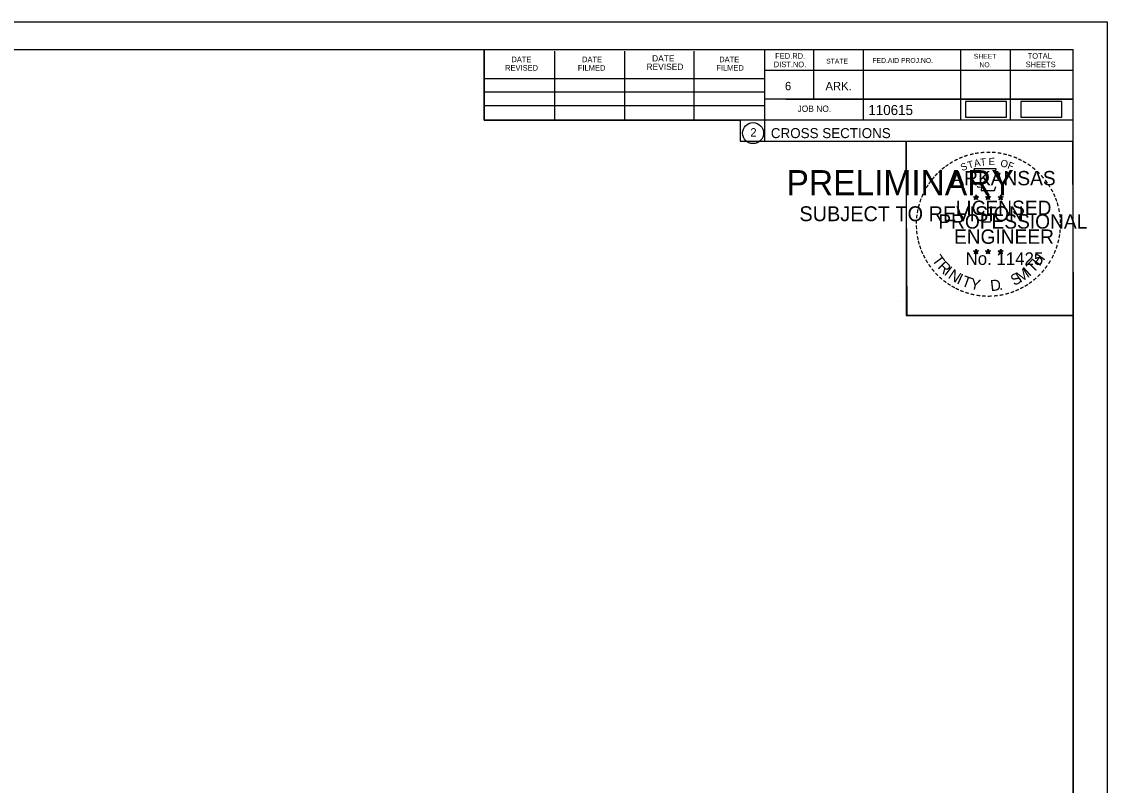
# Model space of a CAD drawing. Extents: x 1372132 to 1372465, y 380083 to 381790.
# Drawn here: x 1372313.3 to 1372464.9, y 381683.5 to 381790.2 of the extents above; entities that cross this region are included whole.
import ezdxf

# ---------------------------------------------------------------- set-up
doc = ezdxf.new("R2010")
doc.units = 0
for name, color, linetype in [('R_Border', 7, 'Continuous'), ('R_Border PE', 7, 'Continuous'), ('R_Border Prem', 7, 'Continuous'), ('R_Erosion', 7, 'Continuous'), ('R_No Plot', 7, 'Continuous')]:
    doc.layers.add(name, color=color, linetype=linetype)

msp = doc.modelspace()

# ---------------------------------------------------------------- linework, layer by layer
at = {"layer": 'R_Border'}
for p, q in [((1372144.01, 381786.3), (1372460.19, 381786.3)), ((1372377.93, 381776.42), (1372377.93, 381786.3)), ((1372387.79, 381776.42), (1372387.79, 381786.1)), ((1372397.55, 381776.42), (1372397.55, 381786.1)), ((1372407.23, 381776.42), (1372407.23, 381786.1)), ((1372417.09, 381786.3), (1372417.09, 381773.5)), ((1372423.93, 381786.3), (1372423.93, 381779.36)), ((1372430.87, 381786.3), (1372430.87, 381776.42)), ((1372444.45, 381786.3), (1372444.45, 381776.42)), ((1372451.39, 381786.3), (1372451.39, 381776.42)), ((1372460.19, 381580.84), (1372460.19, 381786.3)), ((1372377.93, 381782.28), (1372417.09, 381782.28)), ((1372460.19, 381783.36), (1372417.09, 381783.36)), ((1372460.19, 381783.38), (1372460.19, 381783.38)), ((1372377.93, 381780.42), (1372417.09, 381780.42)), ((1372460.19, 381779.36), (1372417.09, 381779.36)), ((1372420.05, 381779.36), (1372460.19, 381779.36)), ((1372377.93, 381776.42), (1372377.93, 381778.48)), ((1372377.93, 381778.48), (1372417.09, 381778.48)), ((1372460.19, 381776.42), (1372377.93, 381776.42)), ((1372417.09, 381773.5), (1372460.19, 381773.5))]:
    msp.add_line(p, q, dxfattribs=at)
msp.add_circle((1372415.48, 381774.63), 1.47, dxfattribs=at)
at = {"layer": 'R_Border PE'}
for p, q in [((1372446.28, 381765.75), (1372446.63, 381765.64)), ((1372446.28, 381765.75), (1372446.53, 381765.71)), ((1372446.28, 381765.75), (1372446.52, 381765.63)), ((1372446.41, 381765.35), (1372446.63, 381765.64)), ((1372446.41, 381765.35), (1372446.54, 381765.59)), ((1372446.41, 381765.35), (1372446.63, 381765.56)), ((1372446.63, 381766.01), (1372446.59, 381765.76)), ((1372446.63, 381765.64), (1372446.63, 381766.01)), ((1372446.63, 381766.01), (1372446.68, 381765.76)), ((1372446.98, 381765.75), (1372446.63, 381765.64)), ((1372446.84, 381765.35), (1372446.63, 381765.64)), ((1372446.84, 381765.35), (1372446.63, 381765.56)), ((1372446.98, 381765.75), (1372446.69, 381765.71)), ((1372446.84, 381765.35), (1372446.7, 381765.64)), ((1372446.98, 381765.75), (1372446.77, 381765.65)), ((1372447.95, 381765.75), (1372448.3, 381765.64)), ((1372447.95, 381765.75), (1372448.2, 381765.71)), ((1372447.95, 381765.75), (1372448.19, 381765.63)), ((1372448.08, 381765.35), (1372448.3, 381765.64)), ((1372448.08, 381765.35), (1372448.21, 381765.59)), ((1372448.08, 381765.35), (1372448.3, 381765.56)), ((1372448.3, 381766.01), (1372448.26, 381765.76)), ((1372448.3, 381765.64), (1372448.3, 381766.01)), ((1372448.3, 381766.01), (1372448.35, 381765.76)), ((1372448.65, 381765.75), (1372448.3, 381765.64)), ((1372448.51, 381765.35), (1372448.3, 381765.64)), ((1372448.51, 381765.35), (1372448.3, 381765.56)), ((1372448.65, 381765.75), (1372448.36, 381765.71)), ((1372448.51, 381765.35), (1372448.37, 381765.64)), ((1372448.65, 381765.75), (1372448.44, 381765.65)), ((1372449.71, 381765.74), (1372450.06, 381765.63)), ((1372449.71, 381765.74), (1372449.97, 381765.7)), ((1372449.71, 381765.74), (1372449.95, 381765.62)), ((1372449.85, 381765.33), (1372450.06, 381765.63)), ((1372449.85, 381765.33), (1372449.97, 381765.58)), ((1372449.85, 381765.33), (1372450.06, 381765.55)), ((1372450.06, 381766), (1372450.02, 381765.74)), ((1372450.06, 381765.63), (1372450.06, 381766)), ((1372450.06, 381766), (1372450.11, 381765.75)), ((1372450.41, 381765.74), (1372450.06, 381765.63)), ((1372450.28, 381765.33), (1372450.06, 381765.63)), ((1372450.28, 381765.33), (1372450.06, 381765.55)), ((1372450.41, 381765.74), (1372450.12, 381765.69)), ((1372450.28, 381765.33), (1372450.14, 381765.63)), ((1372450.41, 381765.74), (1372450.21, 381765.64)), ((1372446.28, 381758.18), (1372446.62, 381758.07)), ((1372446.28, 381758.18), (1372446.53, 381758.14)), ((1372446.28, 381758.18), (1372446.51, 381758.06)), ((1372446.41, 381757.77), (1372446.62, 381758.07)), ((1372446.41, 381757.77), (1372446.53, 381758.02)), ((1372446.41, 381757.77), (1372446.62, 381757.99)), ((1372446.62, 381758.44), (1372446.58, 381758.18)), ((1372446.62, 381758.07), (1372446.62, 381758.44)), ((1372446.62, 381758.44), (1372446.67, 381758.19)), ((1372446.97, 381758.18), (1372446.62, 381758.07)), ((1372446.84, 381757.77), (1372446.62, 381758.07)), ((1372446.84, 381757.77), (1372446.62, 381757.99)), ((1372446.97, 381758.18), (1372446.69, 381758.13)), ((1372446.84, 381757.77), (1372446.7, 381758.06)), ((1372446.97, 381758.18), (1372446.77, 381758.08)), ((1372447.94, 381758.18), (1372448.29, 381758.07)), ((1372447.94, 381758.18), (1372448.2, 381758.14)), ((1372447.94, 381758.18), (1372448.18, 381758.06)), ((1372448.08, 381757.77), (1372448.29, 381758.07)), ((1372448.08, 381757.77), (1372448.2, 381758.02)), ((1372448.08, 381757.77), (1372448.29, 381757.99)), ((1372448.29, 381758.44), (1372448.25, 381758.18)), ((1372448.29, 381758.07), (1372448.29, 381758.44)), ((1372448.29, 381758.44), (1372448.34, 381758.19)), ((1372448.64, 381758.18), (1372448.29, 381758.07)), ((1372448.51, 381757.77), (1372448.29, 381758.07)), ((1372448.51, 381757.77), (1372448.29, 381757.99)), ((1372448.64, 381758.18), (1372448.35, 381758.13)), ((1372448.51, 381757.77), (1372448.37, 381758.06)), ((1372448.64, 381758.18), (1372448.44, 381758.08)), ((1372449.71, 381758.17), (1372450.06, 381758.06)), ((1372449.71, 381758.17), (1372449.96, 381758.13)), ((1372449.71, 381758.17), (1372449.95, 381758.05)), ((1372449.84, 381757.76), (1372450.06, 381758.06)), ((1372449.84, 381757.76), (1372449.97, 381758.01)), ((1372449.84, 381757.76), (1372450.06, 381757.98)), ((1372450.06, 381758.43), (1372450.02, 381758.17)), ((1372450.06, 381758.06), (1372450.06, 381758.43)), ((1372450.06, 381758.43), (1372450.11, 381758.18)), ((1372450.41, 381758.17), (1372450.06, 381758.06)), ((1372450.27, 381757.76), (1372450.06, 381758.06)), ((1372450.27, 381757.76), (1372450.06, 381757.98)), ((1372450.41, 381758.17), (1372450.12, 381758.12)), ((1372450.27, 381757.76), (1372450.14, 381758.05)), ((1372450.41, 381758.17), (1372450.2, 381758.07))]:
    msp.add_line(p, q, dxfattribs=at)
for points in [[(1372446.32, 381769.63), (1372446.59, 381768.81)], [(1372449.83, 381768.71), (1372449.97, 381768.99), (1372449.29, 381768.97), (1372449.44, 381769.63), (1372446.32, 381769.63)], [(1372446.81, 381767.21), (1372446.81, 381767.12), (1372447.38, 381767.1), (1372447.32, 381766.63), (1372449.19, 381766.63), (1372449.39, 381767.17)], [(1372446.63, 381766.01), (1372446.84, 381765.35), (1372446.28, 381765.75), (1372446.98, 381765.75), (1372446.41, 381765.35), (1372446.63, 381766.01)], [(1372448.3, 381766.01), (1372448.51, 381765.35), (1372447.95, 381765.75), (1372448.65, 381765.75), (1372448.08, 381765.35), (1372448.3, 381766.01)], [(1372450.06, 381766), (1372450.28, 381765.33), (1372449.71, 381765.74), (1372450.41, 381765.74), (1372449.85, 381765.33), (1372450.06, 381766)], [(1372446.62, 381758.44), (1372446.84, 381757.77), (1372446.28, 381758.18), (1372446.97, 381758.18), (1372446.41, 381757.77), (1372446.62, 381758.44)], [(1372448.29, 381758.44), (1372448.51, 381757.77), (1372447.94, 381758.18), (1372448.64, 381758.18), (1372448.08, 381757.77), (1372448.29, 381758.44)], [(1372450.06, 381758.43), (1372450.27, 381757.76), (1372449.71, 381758.17), (1372450.41, 381758.17), (1372449.84, 381757.76), (1372450.06, 381758.43)]]:
    msp.add_lwpolyline(points, dxfattribs=at)
for centre, radius in [((1372446.63, 381765.64), 0.172), ((1372446.63, 381765.64), 0.145), ((1372446.63, 381765.64), 0.116), ((1372446.63, 381765.64), 0.0991), ((1372446.63, 381765.64), 0.0747), ((1372446.63, 381765.64), 0.0495), ((1372446.63, 381765.64), 0.0296), ((1372448.3, 381765.64), 0.172), ((1372448.3, 381765.64), 0.145), ((1372448.3, 381765.64), 0.116), ((1372448.3, 381765.64), 0.0991), ((1372448.3, 381765.64), 0.0747), ((1372448.3, 381765.64), 0.0495), ((1372448.3, 381765.64), 0.0296), ((1372450.06, 381765.63), 0.172), ((1372450.06, 381765.63), 0.145), ((1372450.06, 381765.63), 0.116), ((1372450.06, 381765.63), 0.0991), ((1372450.06, 381765.63), 0.0747), ((1372450.06, 381765.63), 0.0495), ((1372450.06, 381765.63), 0.0296), ((1372446.62, 381758.07), 0.172), ((1372446.62, 381758.07), 0.145), ((1372446.62, 381758.07), 0.116), ((1372446.62, 381758.07), 0.0991), ((1372446.62, 381758.07), 0.0747), ((1372446.62, 381758.07), 0.0495), ((1372446.62, 381758.07), 0.0296), ((1372448.29, 381758.07), 0.172), ((1372448.29, 381758.07), 0.145), ((1372448.29, 381758.07), 0.116), ((1372448.29, 381758.07), 0.0991), ((1372448.29, 381758.07), 0.0747), ((1372448.29, 381758.07), 0.0495), ((1372448.29, 381758.07), 0.0296), ((1372450.06, 381758.06), 0.172), ((1372450.06, 381758.06), 0.145), ((1372450.06, 381758.06), 0.116), ((1372450.06, 381758.06), 0.0991), ((1372450.06, 381758.06), 0.0747), ((1372450.06, 381758.06), 0.0495), ((1372450.06, 381758.06), 0.0296)]:
    msp.add_circle(centre, radius, dxfattribs=at)
at = {"layer": 'R_Erosion'}
for points in [[(1372445.13, 381776.84), (1372450.85, 381776.84), (1372450.85, 381779.03), (1372445.13, 381779.03)], [(1372452.88, 381776.84), (1372458.59, 381776.84), (1372458.59, 381779.03), (1372452.88, 381779.03)]]:
    msp.add_lwpolyline(points, close=True, dxfattribs=at)
at = {"layer": 'R_No Plot'}
for p, q in [((1372131.61, 381790.19), (1372464.95, 381790.19)), ((1372436.23, 381751.04), (1372436.23, 381751.04))]:
    msp.add_line(p, q, dxfattribs=at)
for points in [[(1372131.61, 381790.19), (1372464.95, 381790.19), (1372464.95, 381576.86), (1372131.61, 381576.86)], [(1372377.93, 381786.3), (1372377.93, 381776.42), (1372413.67, 381776.42), (1372413.67, 381773.5), (1372436.87, 381773.5), (1372436.87, 381749.17), (1372460.19, 381749.17), (1372460.19, 381580.84), (1372144.01, 381580.84), (1372144.01, 381786.3)], [(1372436.87, 381773.5), (1372460.07, 381773.5), (1372460.19, 381749.17), (1372436.99, 381749.17)]]:
    msp.add_lwpolyline(points, close=True, dxfattribs=at)

# ---------------------------------------------------------------- texts
at = {"layer": 'R_Border'}
for s, height, p in [('DATE', 0.782, (1372381.73, 381784.54)), ('DATE', 0.782, (1372391.59, 381784.54)), ('DATE', 0.879, (1372401.37, 381784.64)), ('DATE', 0.782, (1372410.75, 381784.54)), ('FED.RD.', 0.782, (1372418.57, 381785.02)), ('STATE', 0.684, (1372425.69, 381784.34)), ('FED.AID PROJ.NO.', 0.684, (1372432.15, 381784.44)), ('SHEET', 0.684, (1372446.31, 381785.02)), ('TOTAL', 0.782, (1372453.83, 381785.02)), ('REVISED', 0.782, (1372380.85, 381783.36)), ('FILMED', 0.782, (1372391.01, 381783.36)), ('REVISED', 0.879, (1372400.59, 381783.46)), ('FILMED', 0.782, (1372410.35, 381783.36)), ('DIST.NO.', 0.782, (1372418.37, 381783.84)), ('NO.', 0.684, (1372447.09, 381783.84)), ('SHEETS', 0.782, (1372453.55, 381783.84)), ('6', 1.17, (1372419.93, 381780.62)), ('ARK.', 1.172, (1372425.59, 381780.62)), ('JOB NO.', 0.879, (1372421.69, 381777.6)), ('110615', 1.4, (1372431.57, 381777.16)), ('2', 1.17, (1372415.1, 381774.15)), ('CROSS SECTIONS', 1.4, (1372417.96, 381773.93))]:
    msp.add_text(s, height=height, rotation=360, dxfattribs=at).set_placement(p)
at = {"layer": 'R_Border PE'}
for s, height, rotation, p in [('-', 1.6, 24.3072, (1372444.43, 381770.49)), ('-', 1.6, 19.1761, (1372445.07, 381770.76)), ('-', 1.6, 13.6301, (1372445.82, 381771)), ('-', 1.6, 10.2193, (1372446.5, 381771.16)), ('-', 1.6, 5.8968, (1372447.23, 381771.27)), ('-', 1.6, 0.1862, (1372448, 381771.34)), ('-', 1.6, 357.743, (1372448.72, 381771.33)), ('-', 1.6, 352.1617, (1372449.46, 381771.28)), ('-', 1.6, 347.2049, (1372450.18, 381771.16)), ('-', 1.6, 342.3362, (1372450.82, 381771.01)), ('-', 1.6, 337.8551, (1372451.55, 381770.78)), ('-', 1.6, 38.9507, (1372442.15, 381769.03)), ('-', 1.6, 36.2317, (1372442.63, 381769.41)), ('-', 1.6, 34.0636, (1372443.2, 381769.8)), ('-', 1.6, 28.7918, (1372443.8, 381770.17)), ('S', 1, 21.594, (1372444.68, 381769.31)), ('T', 1, 16.4036, (1372445.59, 381769.64)), ('A', 1, 11.2132, (1372446.42, 381769.89)), ('T', 1, 6.0228, (1372447.26, 381770.06)), ('E', 1, 0.8323, (1372448.37, 381770.17)), ('O', 1, 350.4515, (1372449.97, 381769.96)), ('F', 1, 340.0707, (1372450.93, 381769.73)), ('-', 1.6, 334.1211, (1372452.18, 381770.51)), ('-', 1.6, 329.6409, (1372452.76, 381770.23)), ('-', 1.6, 325.8627, (1372453.41, 381769.87)), ('-', 1.6, 320.5297, (1372454.02, 381769.44)), ('-', 1.6, 50.6142, (1372440.87, 381767.65)), ('-', 1.6, 48.423, (1372441.27, 381768.14)), ('-', 1.6, 42.9622, (1372441.72, 381768.61)), ('ARKANSAS', 2, 360, (1372443.17, 381767.34)), ('-', 1.6, 315.5786, (1372454.62, 381768.95)), ('-', 1.6, 309.8797, (1372455.18, 381768.4)), ('-', 1.6, 62.8713, (1372439.82, 381765.94)), ('-', 1.6, 58.0706, (1372440.13, 381766.56)), ('-', 1.6, 54.2325, (1372440.45, 381767.08)), ('-', 1.6, 306.6522, (1372455.71, 381767.8)), ('-', 1.4, 303.6753, (1372456.2, 381767.23)), ('-', 1.6, 299.6684, (1372456.51, 381766.63)), ('-', 1.6, 72.3945, (1372439.34, 381764.7)), ('-', 1.6, 67.7743, (1372439.56, 381765.33)), ('DWB', 0.01, 360, (1372446.62, 381765.64)), ('DWB', 0.01, 360, (1372448.29, 381765.64)), ('DWB', 0.01, 360, (1372450.05, 381765.63)), ('-', 1.6, 294.6628, (1372456.84, 381766.02)), ('-', 1.6, 290.5728, (1372457.1, 381765.44)), ('-', 1.6, 81.2013, (1372439.01, 381763.27)), ('-', 1.6, 75.461, (1372439.14, 381763.99)), ('LICENSED', 2, 360, (1372443.77, 381763.2)), ('-', 1.6, 285.1233, (1372457.33, 381764.86)), ('-', 1.6, 280.5493, (1372457.53, 381764.12)), ('-', 1.6, 89.0622, (1372438.91, 381761.88)), ('-', 1.6, 85.1863, (1372438.93, 381762.58)), ('PROFESSIONAL', 2, 360, (1372441.35, 381761.29)), ('-', 1.6, 276.5962, (1372457.69, 381763.35)), ('-', 1.6, 274.3301, (1372457.75, 381762.63)), ('-', 1.6, 94.1959, (1372438.94, 381761.16)), ('-', 1.6, 98.9479, (1372439.01, 381760.49)), ('ENGINEER', 2, 360, (1372443.53, 381759.17)), ('-', 1.6, 263.5172, (1372457.77, 381761.33)), ('-', 1.6, 269.9407, (1372457.79, 381761.99)), ('-', 1.6, 101.7149, (1372439.15, 381759.76)), ('-', 1.6, 105.4578, (1372439.31, 381759.16)), ('-', 1.6, 255.7626, (1372457.59, 381760)), ('-', 1.6, 260.9953, (1372457.7, 381760.67)), ('-', 1.6, 109.0874, (1372439.53, 381758.53)), ('-', 1.6, 114.0643, (1372439.78, 381757.93)), ('T', 1.54, 306.0406, (1372440.38, 381756.91)), ('No. 11425', 1.757, 360, (1372445.16, 381756.22)), ('DWB', 0.01, 360, (1372446.61, 381758.07)), ('DWB', 0.01, 360, (1372448.28, 381758.07)), ('DWB', 0.01, 360, (1372450.05, 381758.06)), ('H', 1.54, 54.6088, (1372455.5, 381755.94)), ('-', 1.6, 244.6197, (1372456.92, 381757.97)), ('-', 1.6, 247.8887, (1372457.18, 381758.6)), ('-', 1.6, 252.8681, (1372457.4, 381759.28)), ('-', 1.6, 115.7289, (1372440.09, 381757.32)), ('-', 1.6, 120.4471, (1372440.44, 381756.73)), ('-', 1.6, 125.8934, (1372440.85, 381756.17)), ('R', 1.54, 314.005, (1372441.15, 381755.86)), ('T', 1.54, 46.6444, (1372454.61, 381755)), ('-', 1.6, 233.8452, (1372456.12, 381756.57)), ('-', 1.6, 239.0712, (1372456.53, 381757.22)), ('-', 1.6, 130.7181, (1372441.31, 381755.62)), ('-', 1.6, 134.2238, (1372441.82, 381755.07)), ('I', 1.54, 321.9694, (1372442.05, 381754.93)), ('N', 1.54, 326.5002, (1372442.61, 381754.46)), ('I', 1.54, 335.3603, (1372443.82, 381753.67)), ('T', 1.54, 339.8912, (1372444.48, 381753.34)), ('S', 1.54, 26.9312, (1372451.93, 381753.27)), ('M', 1.54, 32.6563, (1372452.77, 381753.68)), ('I', 1.54, 42.1136, (1372454.05, 381754.52)), ('-', 1.6, 225.7653, (1372455.21, 381755.44)), ('-', 1.6, 231.2538, (1372455.69, 381756)), ('-', 1.6, 138.9338, (1372442.35, 381754.61)), ('-', 1.6, 144.6463, (1372442.91, 381754.2)), ('-', 1.6, 148.0898, (1372443.47, 381753.83)), ('-', 1.6, 151.5704, (1372444.05, 381753.51)), ('Y', 1.54, 347.8556, (1372445.7, 381752.9)), ('D', 1.54, 6.3969, (1372448.69, 381752.54)), ('-', 1.6, 207.3568, (1372453.05, 381753.73)), ('-', 1.6, 212.2491, (1372453.61, 381754.07)), ('-', 1.6, 215.7363, (1372454.14, 381754.46)), ('-', 1.6, 221.0851, (1372454.69, 381754.93)), ('-', 1.6, 154.6002, (1372444.57, 381753.26)), ('-', 1.6, 158.5612, (1372445.19, 381753.01)), ('-', 1.6, 162.7983, (1372445.88, 381752.79)), ('-', 1.6, 167.5555, (1372446.59, 381752.63)), ('-', 1.6, 173.1155, (1372447.37, 381752.52)), ('-', 1.6, 176.5183, (1372448.11, 381752.47)), ('-', 1.6, 181.5918, (1372448.86, 381752.48)), ('-', 1.6, 185.8167, (1372449.67, 381752.56)), ('-', 1.6, 191.2858, (1372450.4, 381752.69)), ('.', 1.54, 13.7642, (1372449.88, 381752.67)), ('-', 1.6, 195.4743, (1372451.13, 381752.89)), ('-', 1.6, 200.7184, (1372451.81, 381753.13)), ('-', 1.6, 204.2516, (1372452.43, 381753.41))]:
    msp.add_text(s, height=height, rotation=rotation, dxfattribs=at).set_placement(p)
at = {"layer": 'R_Border Prem'}
for s, height, p in [('PRELIMINARY', 3.5, (1372420.15, 381765.96)), ('DWB', 0.01, (1372420.89, 381767.81)), ('SUBJECT TO REVISION', 2.0751, (1372421.95, 381762.33))]:
    msp.add_text(s, height=height, rotation=360, dxfattribs=at).set_placement(p)

doc.saveas('drawing.dxf')
